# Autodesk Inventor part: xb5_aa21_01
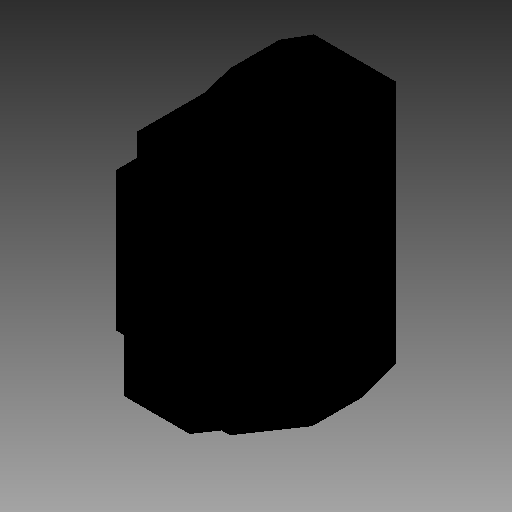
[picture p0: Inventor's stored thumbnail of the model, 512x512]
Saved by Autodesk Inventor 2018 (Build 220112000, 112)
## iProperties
Company: TraceParts S.A.
Created: 2018-05
Part Number: xb5_aa21_01
Checked By: TraceParts S.A.
Material: Generic
Catalog Web Link: www.traceparts.com
Document SubType Name: Modeling
Designer: TraceParts
Density: 1 g/cm^3
Appearance: Default
Author: TraceParts
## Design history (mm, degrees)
feature "xb5_aa21_01.ipt"
body "Solid1"
